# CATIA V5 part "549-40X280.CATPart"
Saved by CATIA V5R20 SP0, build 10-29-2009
Part number: 549-40X280
Definition: NONE
Nomenclature: 549-40X280
Source: Unknown
Description: 549-40X280
Bounding box of the stored display mesh (mm): x 0 to 280, y -22.5 to 22.5, z -22.5 to 22.5
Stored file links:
  C:\Users\Utente\Desktop\IO LAVORO\3D X SITO CF\X SITO\PLASTICA\549\549-40X280.CATPart
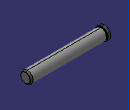
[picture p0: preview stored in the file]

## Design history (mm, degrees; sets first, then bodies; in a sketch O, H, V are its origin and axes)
Body1 "549-40X280" (main body)
  Solid1: solid without history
